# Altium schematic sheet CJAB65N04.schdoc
size 127 x 101 mm
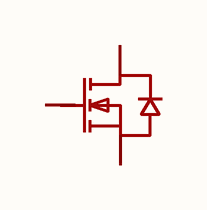
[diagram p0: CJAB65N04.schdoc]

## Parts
Q?  cjab65n04  [PDFNWB-8_L3.3-W3.3-P0.65-BL-EP]  (value not drawn)

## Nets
NetQ?_1: Q?.1(S) Q?.2(S) Q?.3(S)
NetQ?_5: Q?.5(D) Q?.6(D) Q?.7(D) Q?.8(D) Q?.9(D)

Not connected (* = marked no-connect by the designer): Q? 4(G)

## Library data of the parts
Q? = cjab65n04: 数量:1个N沟道;漏源电压(Vdss):40V;连续漏极电流(Id):65A;导通电阻(RDS(on)):6mΩ@10V;耗散功率(Pd):57W;阈值电压(Vgs(th)):2.5V;; Manufacturer: CJ(江苏长电/长晶); AddInBom: yes; ModelId: da4e39fcb4454c0a86b16bc63c48b131; ModelName: PDFNWB-8_L3.3-W3.3-H0.8-P0.65-BL-EP; ModelTransform: 122.047,129.921,0,0,0,0,0,0.005,0; Number: 1个N沟道; Drain to Source Voltage: 40V; Current - Continuous Drain(Id): 65A; Pd - Power Dissipation: 57W; Gate Threshold Voltage (Vgs(th)): 2.5V; Gate Charge(Qg): 54nC@4.5V; Input Capacitance(Ciss): 3.54nF; Reverse Transfer Capacitance (Crss@Vds): 247pF; Type: N沟道; Output Capacitance(Coss): 420pF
